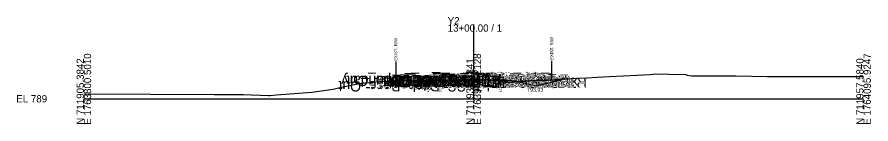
# Model space of a CAD drawing. Extents: x -26 to 1764011, y -10 to 712381.
# Drawn here: x -25.7 to 302.8, y 2990.3 to 3031.5 of the extents above; entities that cross this region are included whole.
import ezdxf

# ---------------------------------------------------------------- set-up
doc = ezdxf.new("R2010")
doc.units = 0
for name, color, linetype in [('Default', 7, 'Continuous'), ('Exist CMT Pavement', 7, 'Continuous'), ('Exist Cross Section Cell', 7, 'Continuous'), ('Exist XS Center Line Elevation Label', 7, 'Continuous'), ('Exist XS Ground Line', 7, 'Continuous'), ('Old_Level_10', 7, 'Continuous'), ('Prop CMT Pvmt Course 1', 7, 'Continuous'), ('Prop CMT Pvmt Course 3', 7, 'Continuous'), ('Prop CMT Pvmt Surface', 7, 'Continuous'), ('Prop CMT Pvmt Surface Shoulder', 7, 'Continuous'), ('Prop CMT Shld Paved Course 1', 7, 'Continuous'), ('Prop CMT Shld Paved Course 3', 7, 'Continuous'), ('Prop CMT Slope Grass', 7, 'Continuous'), ('Prop CMT Subgrade Earthwork', 7, 'Continuous'), ('Prop XS Ditch Standard Text', 7, 'Continuous'), ('Prop XS Earthwork Shape', 7, 'Continuous'), ('Prop XS SE Text', 7, 'Continuous'), ('Prop XS Side Slope Text', 7, 'Continuous'), ('Scratch_Level_7', 7, 'Continuous')]:
    doc.layers.add(name, color=color, linetype=linetype)

msp = doc.modelspace()

# ---------------------------------------------------------------- linework, layer by layer
at = {"layer": 'Exist CMT Pavement'}
msp.add_lwpolyline([(139.45, 3007.03), (140.39, 3007.06), (141.63, 3007.1), (142.93, 3007.13), (143.79, 3007.17), (145.47, 3007.23), (145.95, 3007.24), (148.06, 3007.32), (150.23, 3007.36), (150.56, 3007.37), (151.11, 3007.35), (151.53, 3007.33), (152.48, 3007.3), (153.08, 3007.28), (154.58, 3007.25), (155.62, 3007.23), (156.73, 3007.19), (158.16, 3007.13), (158.89, 3007.11), (160.35, 3007.01)], dxfattribs=at)
at = {"layer": 'Exist Cross Section Cell'}
for p, q in [((150, 3000), (150, 3028.64)), ((0, 3000), (150, 3000)), ((150, 3000), (300, 3000))]:
    msp.add_line(p, q, dxfattribs=at)
at = {"layer": 'Exist XS Ground Line'}
msp.add_lwpolyline([(0, 3001.85), (25.66, 3001.75), (50.12, 3001.66), (50.93, 3001.66), (56.77, 3001.63), (60.44, 3001.63), (61.26, 3001.63), (71.03, 3001.29), (71.65, 3001.28), (74.07, 3001.54), (87.72, 3002.61), (95.93, 3003.72), (98.53, 3004.32), (106.09, 3005.87), (108.08, 3006.12), (117, 3006.9), (131.51, 3007.03), (135.18, 3006.99), (137.17, 3007.01), (137.82, 3007.02), (139.04, 3007.04), (139.47, 3007.04), (140.39, 3007.06), (141.63, 3007.1), (142.93, 3007.13), (143.79, 3007.17), (145.47, 3007.23), (145.95, 3007.24), (148.06, 3007.32), (150.23, 3007.36), (150.56, 3007.37), (151.11, 3007.35), (151.53, 3007.33), (152.48, 3007.3), (153.08, 3007.28), (154.58, 3007.25), (155.62, 3007.23), (156.73, 3007.19), (158.16, 3007.13), (158.89, 3007.11), (160.35, 3007.01), (160.86, 3006.83), (162.11, 3006.21), (166.28, 3006.51), (171.61, 3006.97), (181.32, 3007.31), (187.34, 3007.75), (193.47, 3008.1), (197.49, 3008.28), (202.1, 3008.57), (207.65, 3008.86), (217.87, 3009.4), (219.99, 3009.55), (225.13, 3009.43), (231.6, 3009.29), (232.2, 3009.14), (233.81, 3008.78), (246.14, 3008.8), (250.88, 3008.8), (263.05, 3008.61), (264.6, 3008.61), (278.76, 3008.54), (285.03, 3008.55), (286.55, 3008.56), (294.83, 3008.6), (300, 3008.59)], dxfattribs=at)
at = {"layer": 'Old_Level_10'}
for p, q in [((120, 3014.33), (120, 3006.93)), ((180, 3014.66), (180, 3007.26)), ((137.17, 3007.01), (137.17, 3004.96)), ((160.35, 3007.01), (160.35, 3004.96))]:
    msp.add_line(p, q, dxfattribs=at)
at = {"layer": 'Prop CMT Pvmt Course 1'}
for points in [[(150, 3007.46), (138.54, 3007.13)], [(138.54, 3007.13), (138.54, 3006.88)], [(138.54, 3006.88), (139.45, 3006.91)], [(139.45, 3006.91), (150, 3007.21)], [(139.45, 3006.91), (139.45, 3006.91)], [(150, 3007.21), (150, 3007.46)], [(150, 3007.46), (162, 3007.25)], [(150, 3007.21), (150, 3007.21), (150, 3007.21)], [(160.35, 3007.03), (150, 3007.21)], [(162, 3007), (160.35, 3007.03)], [(160.35, 3007.03), (160.35, 3007.03)], [(162, 3007.25), (162, 3007)]]:
    msp.add_lwpolyline(points, dxfattribs=at)
at = {"layer": 'Prop CMT Pvmt Course 3'}
for points in [[(139.45, 3006.91), (138.54, 3006.88)], [(138.54, 3006.88), (138.54, 3006.47)], [(138.54, 3006.47), (139.45, 3006.49)], [(139.45, 3006.58), (139.45, 3006.91)], [(160.35, 3007.03), (162, 3007)], [(160.35, 3006.7), (160.35, 3007.03)], [(162, 3006.58), (160.35, 3006.61)], [(162, 3007), (162, 3006.58)]]:
    msp.add_lwpolyline(points, dxfattribs=at)
at = {"layer": 'Prop CMT Pvmt Surface'}
for points in [[(150, 3007.46), (138.54, 3007.13)], [(150, 3007.46), (162, 3007.25)]]:
    msp.add_lwpolyline(points, dxfattribs=at)
at = {"layer": 'Prop CMT Pvmt Surface Shoulder'}
for points in [[(138.54, 3007.13), (138.54, 3007.13)], [(162, 3007.25), (162, 3007.25)]]:
    msp.add_lwpolyline(points, dxfattribs=at)
at = {"layer": 'Prop CMT Shld Paved Course 1'}
for points in [[(138.54, 3007.13), (138.29, 3006.88)], [(138.29, 3006.88), (138.54, 3006.88)], [(138.54, 3007.13), (138.54, 3007.13)], [(138.54, 3006.88), (138.54, 3007.13)], [(162, 3007.25), (162, 3007.25)], [(162, 3007.25), (162.26, 3006.99)], [(162, 3007), (162, 3007.25)], [(162.26, 3006.99), (162, 3007)]]:
    msp.add_lwpolyline(points, dxfattribs=at)
at = {"layer": 'Prop CMT Shld Paved Course 3'}
for points in [[(138.29, 3006.88), (137.86, 3006.45)], [(137.86, 3006.45), (138.54, 3006.47)], [(138.54, 3006.88), (138.29, 3006.88)], [(138.54, 3006.55), (138.54, 3006.88)], [(162, 3007), (162.26, 3006.99)], [(162, 3006.67), (162, 3007)], [(162.68, 3006.57), (162, 3006.58)], [(162.26, 3006.99), (162.68, 3006.57)]]:
    msp.add_lwpolyline(points, dxfattribs=at)
at = {"layer": 'Prop CMT Slope Grass'}
for points in [[(138.54, 3007.13), (134.54, 3006.81), (129.93, 3005.66), (124.68, 3006.97)], [(162, 3007.25), (166, 3006.93), (174, 3004.93), (184.44, 3007.54)]]:
    msp.add_lwpolyline(points, dxfattribs=at)
at = {"layer": 'Prop CMT Subgrade Earthwork'}
for p, q in [((137.86, 3006.45), (138.54, 3006.47)), ((139.45, 3006.49), (138.54, 3006.47)), ((139.45, 3007.03), (139.45, 3006.49)), ((160.35, 3006.61), (160.35, 3007.01)), ((160.35, 3006.61), (162, 3006.58)), ((162, 3006.58), (162.68, 3006.57))]:
    msp.add_line(p, q, dxfattribs=at)
for points in [[(137.28, 3007.03), (137.86, 3006.45)], [(163.26, 3007.15), (162.68, 3006.57)]]:
    msp.add_lwpolyline(points, dxfattribs=at)
at = {"layer": 'Prop XS Earthwork Shape'}
for points in [[(134.54, 3006.81), (129.93, 3005.66), (124.68, 3006.97), (131.51, 3007.03), (135.18, 3006.99), (137.04, 3007.01)], [(137.04, 3007.01), (137.17, 3007.01), (137.3, 3007.02), (137.28, 3007.03)], [(139.45, 3006.49), (138.54, 3006.47), (137.86, 3006.45), (137.3, 3007.02), (137.82, 3007.02), (139.04, 3007.04), (139.45, 3007.03)], [(160.35, 3006.61), (161.34, 3006.59), (160.86, 3006.83), (160.35, 3007.01)], [(162, 3006.58), (162.68, 3006.57), (163.26, 3007.15), (166, 3006.93), (167.32, 3006.6), (166.28, 3006.51), (162.11, 3006.21), (161.34, 3006.59)], [(174, 3004.93), (184.44, 3007.54), (181.32, 3007.31), (171.61, 3006.97), (167.32, 3006.6)]]:
    msp.add_lwpolyline(points, close=True, dxfattribs=at)

# ---------------------------------------------------------------- texts
at = {"layer": 'Default'}
msp.add_text('-', height=0.0001, dxfattribs=at).set_placement((0, 3000))
at = {"layer": 'Exist Cross Section Cell'}
for s, p in [('Y2', (140, 3028.64)), ('13+00.00 / 1', (140, 3025.84)), ('EL 789', (-26, 2998.6))]:
    msp.add_text(s, height=2.8, dxfattribs=at).set_placement(p)
for s, p in [('E 1763800.5010', (2.8, 2990)), ('E 1763948.2128', (152.8, 2990)), ('E 1764095.9247', (302.8, 2990)), ('N 711905.3842', (0, 2990)), ('N 711931.4841', (150, 2990)), ('N 711957.5840', (300, 2990))]:
    msp.add_text(s, height=2.8, rotation=90, dxfattribs=at).set_placement(p)
at = {"layer": 'Exist XS Center Line Elevation Label'}
msp.add_text('796.36', height=1, dxfattribs=at).set_placement((147.86, 3005.36))
at = {"layer": 'Old_Level_10'}
for s, height, p in [('EXIST. R/W', 1.181, (120.59, 3014.63)), ('EXIST. R/W', 1.181, (180.59, 3014.97)), ('EOP', 0.787, (137.56, 3002.57)), ('EOP', 0.787, (160.74, 3002.56))]:
    msp.add_text(s, height=height, rotation=90, dxfattribs=at).set_placement(p)
at = {"layer": 'Prop XS Ditch Standard Text'}
for s, p in [('794.66', (127.29, 3003.41)), ('793.93', (170.47, 3002.7))]:
    msp.add_text(s, height=1.5, dxfattribs=at).set_placement(p)
at = {"layer": 'Prop XS SE Text'}
for s, rotation, p in [('0.029', 1.6611, (141.64, 3008.22)), ('0.018', 358.9688, (153.59, 3008.4))]:
    msp.add_text(s, height=1.5, rotation=rotation, dxfattribs=at).set_placement(p)
at = {"layer": 'Prop XS Side Slope Text'}
for rotation, p in [(345.9638, (126.1, 3007.39)), (14.0362, (130.95, 3006.69)), (345.9638, (165.69, 3007.78)), (14.0362, (175.74, 3006.42))]:
    msp.add_text('4:1', height=1.5, rotation=rotation, dxfattribs=at).set_placement(p)
at = {"layer": 'Scratch_Level_7'}
for s, p in [('Exterior Boundary', (141.92, 3008.91)), ('LT_Slope_Cut', (135.21, 3008.91)), ('LT_GS_OS_CTL', (154.16, 3008.81)), ('LT_PS3_Shelf_Out', (162.13, 3008.54)), ('LT_PV1_OEEOP', (159.15, 3008.91)), ('LT_PV1_OEOT', (156.18, 3009.13)), ('LT_PS1_OEOP', (156.45, 3009.13)), ('LT_PV2_OEEOP', (160.16, 3008.91)), ('LT_PV3_OEEOP', (160.19, 3008.58)), ('LT_Sub_OEEOP', (159.62, 3008.24)), ('LT_PS3_OEOP', (156.89, 3008.54)), ('LT_PS2_OEOP', (157.2, 3008.88)), ('LT_PV2_OEOT', (157.19, 3008.88)), ('LT_PV3_OEOT', (157.22, 3008.55)), ('LT_Sub_OEOT', (156.65, 3008.22)), ('RT_PV1_IEEOP', (169.32, 3009.21)), ('LT_PV1_IEEOP', (168.82, 3009.21)), ('RT_PV2_IEEOP', (170.33, 3009.21)), ('LT_PV2_IEEOP', (169.82, 3009.21)), ('PV1_PGL', (160.68, 3009.46)), ('PV2_PGL', (161.68, 3009.21)), ('RT_Sub_Trench_Out', (188.88, 3008.31)), ('RT_PV1_OEEOP', (180.55, 3009.03)), ('RT_PV2_OEEOP', (181.56, 3009.03)), ('RT_PV3_OEEOP', (181.59, 3008.7)), ('RT_Sub_OEEOP', (181.02, 3008.36)), ('RT_PS3_Shelf_Out', (187.28, 3008.65)), ('RT_PV1_OEOT', (180.14, 3009.25)), ('RT_PS1_OEOP', (180.41, 3009.25)), ('RT_PV2_OEOT', (181.15, 3009)), ('RT_PV3_OEOT', (181.18, 3008.67)), ('RT_Sub_OEOT', (180.61, 3008.33)), ('RT_PS2_OEOP', (181.67, 3008.99)), ('RT_PS3_OEOP', (182.04, 3008.65)), ('RT_GS_OS_CTL', (186.12, 3008.93)), ('Exterior Boundary', (193.67, 3008.19)), ('RT_Slope_Fill', (185.09, 3008.6)), ('LT_SS_Ditch_Base_Out', (156.27, 3006.81)), ('LT_Sub_OSS_DLT', (154.56, 3008.08)), ('LT_Sub_Trench_Out', (163.05, 3008.2)), ('RT_Sub_OSS_DLT', (193.35, 3008.19))]:
    msp.add_text(s, height=4, rotation=180, dxfattribs=at).set_placement(p)

doc.saveas('drawing.dxf')
